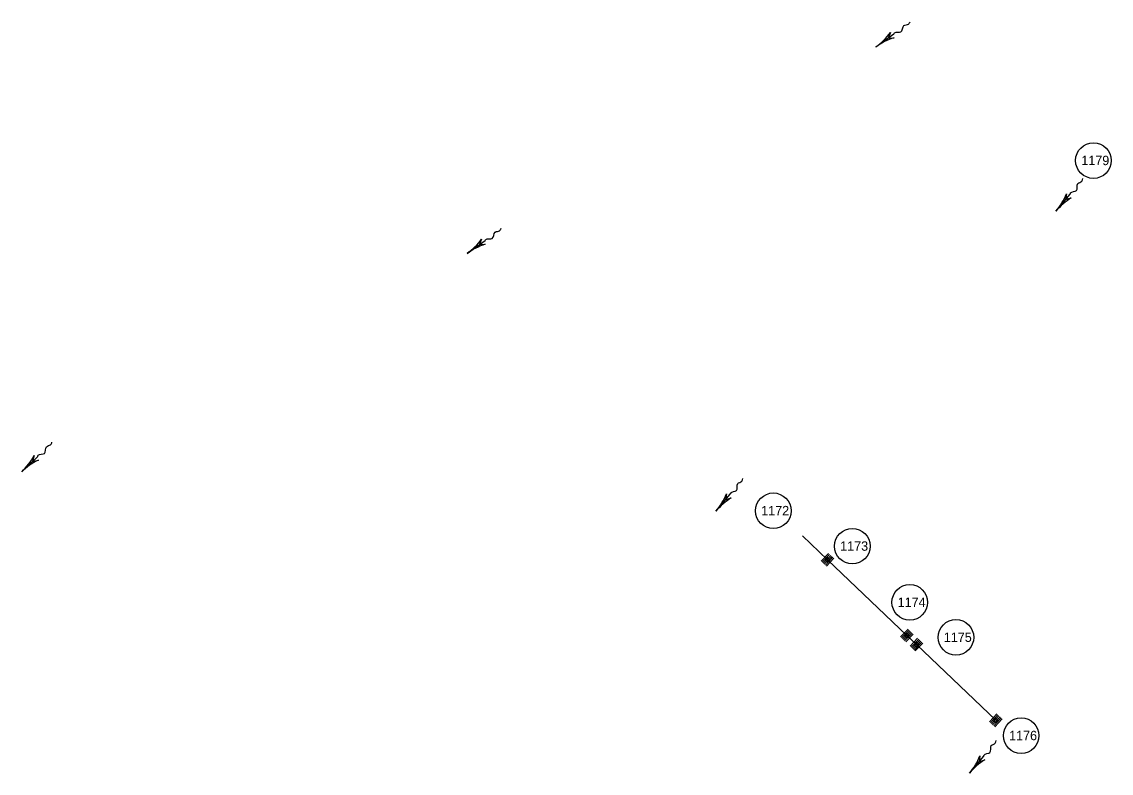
# Model space of a CAD drawing. Extents: x 594534 to 598564, y 225861 to 236229.
# Drawn here: x 596572 to 597267, y 231375 to 231855 of the extents above; entities that cross this region are included whole.
import ezdxf

# ---------------------------------------------------------------- set-up
doc = ezdxf.new("R2010")
doc.units = 0
for name, color, linetype in [('P_DRN_Flow', 7, 'Continuous'), ('P_DRN_Inlet', 7, 'Continuous'), ('P_DRN_SS_UG', 7, 'Continuous'), ('P_DRN_Text', 7, 'Continuous')]:
    doc.layers.add(name, color=color, linetype=linetype)

msp = doc.modelspace()

# ---------------------------------------------------------------- linework, layer by layer
at = {"layer": 'P_DRN_Flow'}
for p, q in [((597117.12, 231839.09), (597128.59, 231847.34)), ((597232.03, 231734.18), (597241.1, 231745.01)), ((596856.16, 231707.22), (596867.63, 231715.47)), ((596571.83, 231567.78), (596582, 231577.58)), ((597014.97, 231542.6), (597024.04, 231553.43)), ((597176.81, 231375.31), (597185.89, 231386.14))]:
    msp.add_line(p, q, dxfattribs=at)
for points in [[(597126.34, 231848.18), (597124.91, 231844.69), (597128.67, 231844.94)], [(597238.71, 231745.27), (597238.19, 231741.54), (597241.78, 231742.71)], [(596865.38, 231716.31), (596863.95, 231712.82), (596867.72, 231713.07)], [(596579.65, 231578.1), (596578.73, 231574.44), (596582.43, 231575.22)], [(597021.65, 231553.69), (597021.13, 231549.95), (597024.72, 231551.13)], [(597183.5, 231386.4), (597182.97, 231382.67), (597186.56, 231383.84)]]:
    msp.add_lwpolyline(points, dxfattribs=at)
for centre, start, end in [((597092.62, 231873.15), 305.71973, 323.48205), ((597141.61, 231805.02), 107.95741, 125.71973), ((597199.87, 231761.12), 320.04245, 337.80477), ((597264.19, 231707.23), 122.28013, 140.04245), ((596831.67, 231741.28), 305.71973, 323.48205), ((596880.66, 231673.15), 107.95741, 125.71973), ((596542.71, 231597.98), 313.94896, 331.71128), ((596600.95, 231537.57), 116.18664, 133.94896), ((596982.81, 231569.54), 320.04245, 337.80477), ((597047.13, 231515.65), 122.28013, 140.04245), ((597144.65, 231402.26), 320.04245, 337.80477), ((597208.97, 231348.36), 122.28013, 140.04245)]:
    msp.add_arc(centre, 41.96, start, end, dxfattribs=at)
for points in [[(597128.59, 231847.34), (597129.04, 231848.05), (597133.07, 231848.63), (597134.98, 231852.7), (597137.82, 231853.59), (597138.85, 231855.11)], [(597241.11, 231745.01), (597241.37, 231745.81), (597245.13, 231747.37), (597245.97, 231751.79), (597248.5, 231753.35), (597249.13, 231755.08)], [(596867.63, 231715.47), (596868.09, 231716.18), (596872.12, 231716.76), (596874.02, 231720.83), (596876.87, 231721.72), (596877.9, 231723.24)], [(596582, 231577.58), (596582.35, 231578.35), (596586.25, 231579.5), (596587.55, 231583.81), (596590.24, 231585.09), (596591.05, 231586.74)], [(597024.04, 231553.43), (597024.31, 231554.23), (597028.07, 231555.79), (597028.91, 231560.21), (597031.44, 231561.77), (597032.07, 231563.5)], [(597185.89, 231386.14), (597186.15, 231386.94), (597189.91, 231388.5), (597190.75, 231392.92), (597193.28, 231394.48), (597193.91, 231396.21)]]:
    msp.add_spline(points, degree=3, dxfattribs=at)
at = {"layer": 'P_DRN_Inlet'}
for p, q in [((597082.18, 231510.61), (597086.89, 231515.62)), ((597082.84, 231510), (597087.54, 231515.01)), ((597083.49, 231509.38), (597088.2, 231514.39)), ((597084.15, 231508.76), (597088.86, 231513.77)), ((597084.8, 231508.15), (597089.51, 231513.16)), ((597085.46, 231507.53), (597090.17, 231512.54)), ((597132.82, 231462.34), (597137.58, 231467.3)), ((597133.47, 231461.71), (597138.23, 231466.68)), ((597134.13, 231461.09), (597138.88, 231466.06)), ((597134.78, 231460.47), (597139.53, 231465.44)), ((597135.43, 231459.85), (597140.18, 231464.81)), ((597136.08, 231459.22), (597140.83, 231464.19)), ((597138.98, 231456.47), (597143.73, 231461.44)), ((597139.63, 231455.85), (597144.38, 231460.81)), ((597140.28, 231455.22), (597145.03, 231460.19)), ((597140.93, 231454.6), (597145.68, 231459.57)), ((597141.58, 231453.98), (597146.33, 231458.95)), ((597142.23, 231453.36), (597146.98, 231458.32)), ((597189.64, 231408.1), (597194.33, 231413.13)), ((597190.3, 231407.49), (597194.98, 231412.51)), ((597190.95, 231406.87), (597195.64, 231411.9)), ((597191.61, 231406.26), (597196.3, 231411.29)), ((597192.27, 231405.64), (597196.96, 231410.67)), ((597192.93, 231405.03), (597197.62, 231410.06))]:
    msp.add_line(p, q, dxfattribs=at)
for points in [[(597086.22, 231510.16), (597087.59, 231511.62), (597086.13, 231512.99), (597084.76, 231511.53)], [(597136.86, 231461.85), (597138.24, 231463.29), (597136.8, 231464.68), (597135.41, 231463.23)], [(597143.01, 231455.98), (597144.39, 231457.43), (597142.95, 231458.81), (597141.56, 231457.37)], [(597193.68, 231407.67), (597195.04, 231409.13), (597193.58, 231410.49), (597192.21, 231409.03)]]:
    msp.add_lwpolyline(points, close=True, dxfattribs=at)
at = {"layer": 'P_DRN_SS_UG'}
for p, q in [((597086.17, 231511.58), (597070.16, 231526.85)), ((597142.98, 231457.4), (597136.83, 231463.26)), ((597193.63, 231409.08), (597142.98, 231457.4))]:
    msp.add_line(p, q, dxfattribs=at)
msp.add_lwpolyline([(597136.83, 231463.26), (597086.17, 231511.58)], dxfattribs=at)
at = {"layer": 'P_DRN_Text'}
for centre in [(597255.93, 231766.48), (597051.6, 231542.89), (597102.01, 231520.27), (597138.68, 231484.4), (597168.16, 231462.06), (597209.82, 231399.31)]:
    msp.add_circle(centre, 11.36, dxfattribs=at)

# ---------------------------------------------------------------- texts
for s, p in [('1179', (597248.2, 231763.56)), ('1172', (597043.86, 231539.97)), ('1173', (597094.27, 231517.36)), ('1174', (597130.95, 231481.48)), ('1175', (597160.43, 231459.14)), ('1176', (597202.09, 231396.39))]:
    msp.add_text(s, height=6, dxfattribs=at).set_placement(p)

doc.saveas('drawing.dxf')
